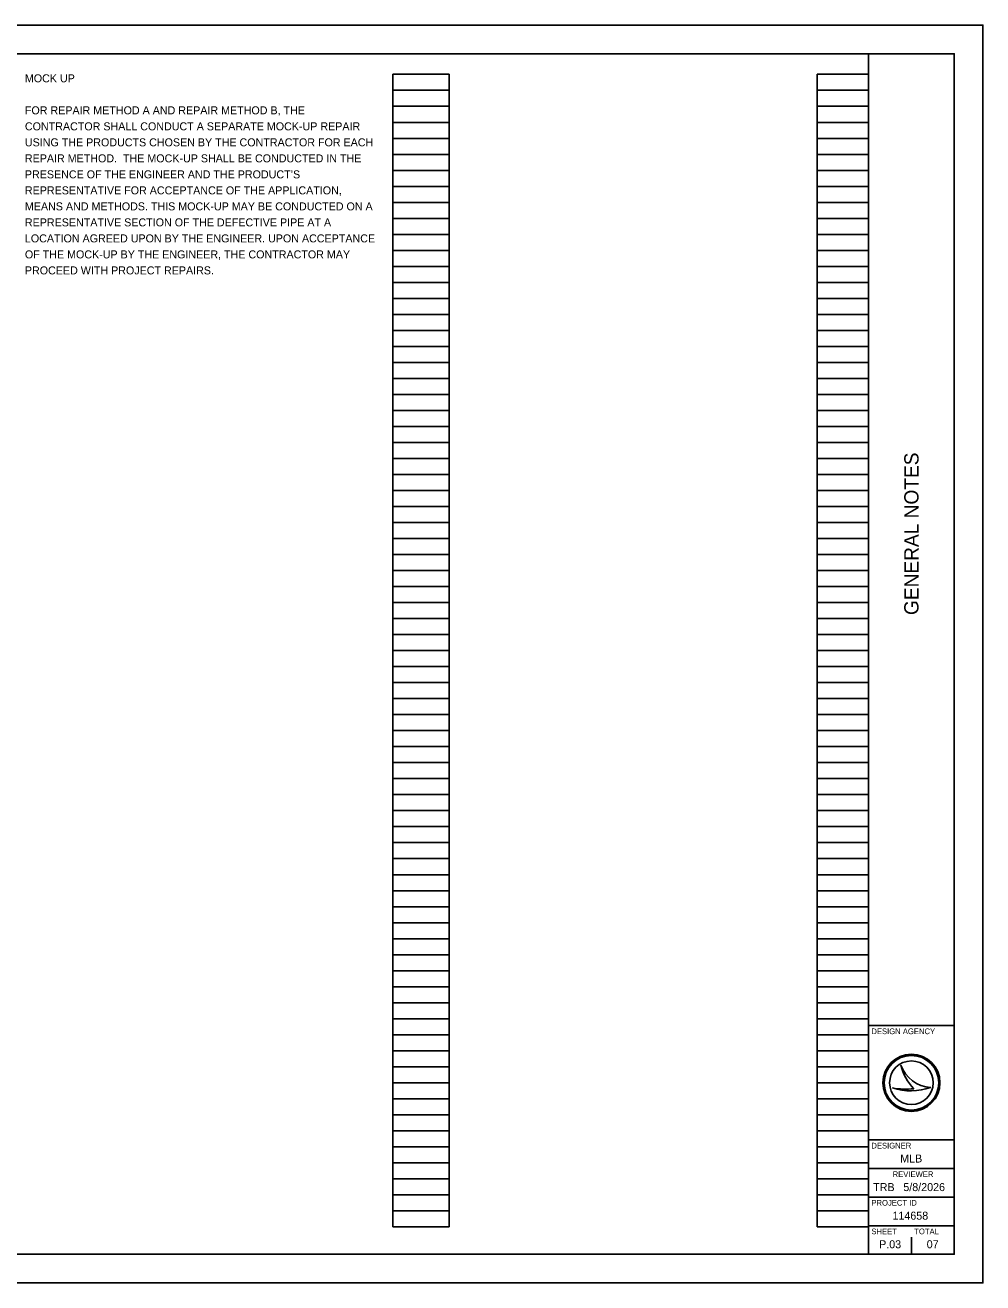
# Model space of a CAD drawing. Extents: x 0 to 34, y -22.7 to 22.
# Drawn here: x 17.24 to 34, y 0 to 22 of the extents above; entities that cross this region are included whole.
import ezdxf

# ---------------------------------------------------------------- set-up
doc = ezdxf.new("R2010")
doc.units = 0
for name, color, linetype in [('SH_Border', 7, 'Continuous'), ('SH_Cut_Line', 7, 'Continuous'), ('SH_Data', 7, 'Continuous'), ('SH_Text', 7, 'Continuous')]:
    doc.layers.add(name, color=color, linetype=linetype)

msp = doc.modelspace()

# ---------------------------------------------------------------- linework, layer by layer
at = {"layer": 'SH_Border'}
for p, q in [((32, 0.5), (32, 21.5)), ((32, 4.5), (33.5, 4.5)), ((32, 2.5), (33.5, 2.5)), ((32, 2), (33.5, 2)), ((32, 1.5), (33.5, 1.5)), ((32, 1), (33.5, 1))]:
    msp.add_line(p, q, dxfattribs=at)
msp.add_lwpolyline([(1.5, 21.5), (33.5, 21.5), (33.5, 0.5), (1.5, 0.5)], close=True, dxfattribs=at)
at = {"layer": 'SH_Cut_Line'}
msp.add_lwpolyline([(0, 0), (34, 0), (34, 22), (0, 22)], close=True, dxfattribs=at)
at = {"layer": 'SH_Data'}
for p, q in [((23.68, 0.98), (23.68, 21.14)), ((23.68, 21.14), (24.66, 21.14)), ((24.66, 0.98), (24.66, 21.14)), ((31.1, 0.98), (31.1, 21.14)), ((31.1, 21.14), (32, 21.14)), ((32, 0.98), (32, 21.14)), ((23.68, 20.86), (24.66, 20.86)), ((31.1, 20.86), (32, 20.86)), ((23.68, 20.58), (24.66, 20.58)), ((31.1, 20.58), (32, 20.58)), ((23.68, 20.3), (24.66, 20.3)), ((31.1, 20.3), (32, 20.3)), ((23.68, 20.02), (24.66, 20.02)), ((31.1, 20.02), (32, 20.02)), ((23.68, 19.74), (24.66, 19.74)), ((31.1, 19.74), (32, 19.74)), ((23.68, 19.46), (24.66, 19.46)), ((31.1, 19.46), (32, 19.46)), ((23.68, 19.18), (24.66, 19.18)), ((31.1, 19.18), (32, 19.18)), ((23.68, 18.9), (24.66, 18.9)), ((31.1, 18.9), (32, 18.9)), ((23.68, 18.62), (24.66, 18.62)), ((31.1, 18.62), (32, 18.62)), ((23.68, 18.34), (24.66, 18.34)), ((31.1, 18.34), (32, 18.34)), ((23.68, 18.06), (24.66, 18.06)), ((31.1, 18.06), (32, 18.06)), ((23.68, 17.78), (24.66, 17.78)), ((31.1, 17.78), (32, 17.78)), ((23.68, 17.5), (24.66, 17.5)), ((31.1, 17.5), (32, 17.5)), ((23.68, 17.22), (24.66, 17.22)), ((31.1, 17.22), (32, 17.22)), ((23.68, 16.94), (24.66, 16.94)), ((31.1, 16.94), (32, 16.94)), ((23.68, 16.66), (24.66, 16.66)), ((31.1, 16.66), (32, 16.66)), ((23.68, 16.38), (24.66, 16.38)), ((31.1, 16.38), (32, 16.38)), ((23.68, 16.1), (24.66, 16.1)), ((31.1, 16.1), (32, 16.1)), ((23.68, 15.82), (24.66, 15.82)), ((31.1, 15.82), (32, 15.82)), ((23.68, 15.54), (24.66, 15.54)), ((31.1, 15.54), (32, 15.54)), ((23.68, 15.26), (24.66, 15.26)), ((31.1, 15.26), (32, 15.26)), ((23.68, 14.98), (24.66, 14.98)), ((31.1, 14.98), (32, 14.98)), ((23.68, 14.7), (24.66, 14.7)), ((31.1, 14.7), (32, 14.7)), ((23.68, 14.42), (24.66, 14.42)), ((31.1, 14.42), (32, 14.42)), ((23.68, 14.14), (24.66, 14.14)), ((31.1, 14.14), (32, 14.14)), ((23.68, 13.86), (24.66, 13.86)), ((31.1, 13.86), (32, 13.86)), ((23.68, 13.58), (24.66, 13.58)), ((31.1, 13.58), (32, 13.58)), ((23.68, 13.3), (24.66, 13.3)), ((31.1, 13.3), (32, 13.3)), ((23.68, 13.02), (24.66, 13.02)), ((31.1, 13.02), (32, 13.02)), ((23.68, 12.74), (24.66, 12.74)), ((31.1, 12.74), (32, 12.74)), ((23.68, 12.46), (24.66, 12.46)), ((31.1, 12.46), (32, 12.46)), ((23.68, 12.18), (24.66, 12.18)), ((31.1, 12.18), (32, 12.18)), ((23.68, 11.9), (24.66, 11.9)), ((31.1, 11.9), (32, 11.9)), ((23.68, 11.62), (24.66, 11.62)), ((31.1, 11.62), (32, 11.62)), ((23.68, 11.34), (24.66, 11.34)), ((31.1, 11.34), (32, 11.34)), ((23.68, 11.06), (24.66, 11.06)), ((31.1, 11.06), (32, 11.06)), ((23.68, 10.78), (24.66, 10.78)), ((31.1, 10.78), (32, 10.78)), ((23.68, 10.5), (24.66, 10.5)), ((31.1, 10.5), (32, 10.5)), ((23.68, 10.22), (24.66, 10.22)), ((31.1, 10.22), (32, 10.22)), ((23.68, 9.94), (24.66, 9.94)), ((31.1, 9.94), (32, 9.94)), ((23.68, 9.66), (24.66, 9.66)), ((31.1, 9.66), (32, 9.66)), ((23.68, 9.38), (24.66, 9.38)), ((31.1, 9.38), (32, 9.38)), ((23.68, 9.1), (24.66, 9.1)), ((31.1, 9.1), (32, 9.1)), ((23.68, 8.82), (24.66, 8.82)), ((31.1, 8.82), (32, 8.82)), ((23.68, 8.54), (24.66, 8.54)), ((31.1, 8.54), (32, 8.54)), ((23.68, 8.26), (24.66, 8.26)), ((31.1, 8.26), (32, 8.26)), ((23.68, 7.98), (24.66, 7.98)), ((31.1, 7.98), (32, 7.98)), ((23.68, 7.7), (24.66, 7.7)), ((31.1, 7.7), (32, 7.7)), ((23.68, 7.42), (24.66, 7.42)), ((31.1, 7.42), (32, 7.42)), ((23.68, 7.14), (24.66, 7.14)), ((31.1, 7.14), (32, 7.14)), ((23.68, 6.86), (24.66, 6.86)), ((31.1, 6.86), (32, 6.86)), ((23.68, 6.58), (24.66, 6.58)), ((31.1, 6.58), (32, 6.58)), ((23.68, 6.3), (24.66, 6.3)), ((31.1, 6.3), (32, 6.3)), ((23.68, 6.02), (24.66, 6.02)), ((31.1, 6.02), (32, 6.02)), ((23.68, 5.74), (24.66, 5.74)), ((31.1, 5.74), (32, 5.74)), ((23.68, 5.46), (24.66, 5.46)), ((31.1, 5.46), (32, 5.46)), ((23.68, 5.18), (24.66, 5.18)), ((31.1, 5.18), (32, 5.18)), ((23.68, 4.9), (24.66, 4.9)), ((31.1, 4.9), (32, 4.9)), ((23.68, 4.62), (24.66, 4.62)), ((31.1, 4.62), (32, 4.62)), ((23.68, 4.34), (24.66, 4.34)), ((31.1, 4.34), (32, 4.34)), ((23.68, 4.06), (24.66, 4.06)), ((31.1, 4.06), (32, 4.06)), ((23.68, 3.78), (24.66, 3.78)), ((31.1, 3.78), (32, 3.78)), ((32.567, 3.81), (32.567, 3.81)), ((23.68, 3.5), (24.66, 3.5)), ((31.1, 3.5), (32, 3.5)), ((32.417, 3.41), (32.417, 3.41)), ((32.75, 3.5), (32.75, 3.5)), ((33.087, 3.419), (33.087, 3.419)), ((23.68, 3.22), (24.66, 3.22)), ((31.1, 3.22), (32, 3.22)), ((23.68, 2.94), (24.66, 2.94)), ((31.1, 2.94), (32, 2.94)), ((23.68, 2.66), (24.66, 2.66)), ((31.1, 2.66), (32, 2.66)), ((23.68, 2.38), (24.66, 2.38)), ((31.1, 2.38), (32, 2.38)), ((23.68, 2.1), (24.66, 2.1)), ((31.1, 2.1), (32, 2.1)), ((23.68, 1.82), (24.66, 1.82)), ((31.1, 1.82), (32, 1.82)), ((23.68, 1.54), (24.66, 1.54)), ((31.1, 1.54), (32, 1.54)), ((23.68, 1.26), (24.66, 1.26)), ((31.1, 1.26), (32, 1.26)), ((23.68, 0.98), (24.66, 0.98)), ((31.1, 0.98), (32, 0.98)), ((32.375, 0.675), (32.375, 0.675)), ((32.75, 0.5), (32.75, 0.8))]:
    msp.add_line(p, q, dxfattribs=at)
for radius in [0.5, 0.477, 0.477, 0.382]:
    msp.add_circle((32.75, 3.5), radius, dxfattribs=at)
for centre, radius, start, end in [((33.116, 3.998), 0.58, 198.9257, 198.9319), ((33.347, 3.97), 0.796, 191.6379, 191.6421), ((33.116, 3.998), 0.58, 198.9319, 267.1657), ((33.347, 3.97), 0.796, 191.6421, 226.0947), ((32.739, 4.37), 1.013, 251.4576, 290.0832), ((32.648, 4.654), 1.266, 259.4964, 259.4995), ((32.739, 4.37), 1.013, 251.4527, 251.4576), ((32.648, 4.654), 1.266, 259.4995, 276.6672)]:
    msp.add_arc(centre, radius, start, end, dxfattribs=at)

# ---------------------------------------------------------------- texts
msp.add_text('GENERAL NOTES', height=0.25, rotation=90, dxfattribs=at).set_placement((32.875, 11.682))
for s, height, p in [('DESIGN AGENCY', 0.1, (32.05, 4.35)), ('DESIGNER', 0.1, (32.05, 2.35)), ('MLB', 0.14, (32.554, 2.105)), ('REVIEWER', 0.1, (32.422, 1.85)), ('TRB', 0.14, (32.081, 1.605)), ('5/8/2026', 0.14, (32.609, 1.605)), ('PROJECT ID', 0.1, (32.05, 1.35)), ('114658', 0.14, (32.419, 1.105)), ('SHEET', 0.1, (32.05, 0.85)), ('TOTAL', 0.1, (32.8, 0.85)), ('P.03', 0.14, (32.185, 0.605)), ('07', 0.14, (33.018, 0.605))]:
    msp.add_text(s, height=height, dxfattribs=at).set_placement(p)
at = {"layer": 'SH_Text'}
for s, p in [('MOCK UP', (17.24, 21)), ('FOR REPAIR METHOD A AND REPAIR METHOD B, THE ', (17.24, 20.44)), ('CONTRACTOR SHALL CONDUCT A SEPARATE MOCK-UP REPAIR ', (17.24, 20.16)), ('USING THE PRODUCTS CHOSEN BY THE CONTRACTOR FOR EACH ', (17.24, 19.88)), ('REPAIR METHOD.  THE MOCK-UP SHALL BE CONDUCTED IN THE ', (17.24, 19.6)), ('PRESENCE OF THE ENGINEER AND THE PRODUCT’S ', (17.24, 19.32)), ('REPRESENTATIVE FOR ACCEPTANCE OF THE APPLICATION, ', (17.24, 19.04)), ('MEANS AND METHODS. THIS MOCK-UP MAY BE CONDUCTED ON A ', (17.24, 18.76)), ('REPRESENTATIVE SECTION OF THE DEFECTIVE PIPE AT A ', (17.24, 18.48)), ('LOCATION AGREED UPON BY THE ENGINEER. UPON ACCEPTANCE ', (17.24, 18.2)), ('OF THE MOCK-UP BY THE ENGINEER, THE CONTRACTOR MAY ', (17.24, 17.92)), ('PROCEED WITH PROJECT REPAIRS. ', (17.24, 17.64))]:
    msp.add_text(s, height=0.14, dxfattribs=at).set_placement(p)

doc.saveas('drawing.dxf')
